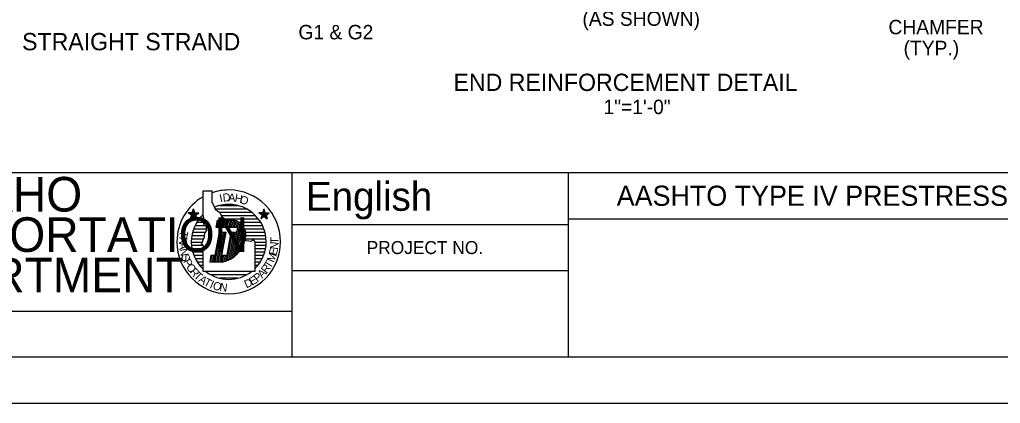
# Model space of a CAD drawing. Extents: x 0 to 45.3, y 0 to 31.4.
# Drawn here: x 21.72 to 35.92, y 0 to 5.54 of the extents above; entities that cross this region are included whole.
import ezdxf

# ---------------------------------------------------------------- set-up
doc = ezdxf.new("R2010")
doc.units = 0
for name, color, linetype in [('BORDER_ANNO_Cutsheet', 7, 'Continuous'), ('BRDG_ANNO_Anno-Sheet', 7, 'Continuous'), ('BRDG_ANNO_General-Notes', 7, 'Continuous')]:
    doc.layers.add(name, color=color, linetype=linetype)

msp = doc.modelspace()

# ---------------------------------------------------------------- linework, layer by layer
at = {"layer": 'BORDER_ANNO_Cutsheet'}
msp.add_lwpolyline([(0, 29.333), (45.333, 29.333), (45.333, 0), (0, 0)], close=True, dxfattribs=at)
at = {"layer": 'BRDG_ANNO_Anno-Sheet'}
for p, q in [((2, 3.333), (25.667, 3.333)), ((25.667, 0.667), (25.667, 3.333)), ((25.667, 3.333), (44.667, 3.333)), ((29.667, 0.667), (29.667, 3.333)), ((24.379, 2.723), (24.379, 3.071)), ((24.379, 3.071), (24.511, 3.071)), ((24.511, 2.897), (24.511, 3.071)), ((24.511, 2.897), (24.546, 2.835)), ((24.62, 2.859), (24.877, 2.859)), ((24.268, 2.72), (24.163, 2.754)), ((24.221, 2.754), (24.163, 2.754)), ((24.21, 2.72), (24.163, 2.754)), ((24.258, 2.754), (24.192, 2.664)), ((24.21, 2.72), (24.192, 2.664)), ((24.239, 2.698), (24.192, 2.664)), ((24.21, 2.72), (24.316, 2.754)), ((24.221, 2.754), (24.239, 2.809)), ((24.221, 2.754), (24.287, 2.664)), ((24.239, 2.698), (24.239, 2.809)), ((24.258, 2.754), (24.239, 2.809)), ((24.239, 2.698), (24.287, 2.664)), ((24.258, 2.754), (24.316, 2.754)), ((24.268, 2.72), (24.316, 2.754)), ((24.268, 2.72), (24.287, 2.664)), ((24.366, 2.715), (24.382, 2.715)), ((24.392, 2.675), (24.379, 2.723)), ((24.546, 2.835), (24.552, 2.807)), ((24.552, 2.807), (24.622, 2.758)), ((24.556, 2.811), (25.001, 2.811)), ((24.62, 2.763), (25.076, 2.763)), ((24.622, 2.758), (24.643, 2.703)), ((24.638, 2.715), (25.134, 2.715)), ((24.643, 2.703), (24.712, 2.647)), ((25.29, 2.72), (25.184, 2.754)), ((25.232, 2.72), (25.184, 2.754)), ((25.242, 2.754), (25.184, 2.754)), ((25.279, 2.754), (25.213, 2.664)), ((25.232, 2.72), (25.213, 2.664)), ((25.261, 2.698), (25.213, 2.664)), ((25.232, 2.72), (25.337, 2.754)), ((25.242, 2.754), (25.261, 2.809)), ((25.242, 2.754), (25.308, 2.664)), ((25.261, 2.698), (25.261, 2.809)), ((25.279, 2.754), (25.261, 2.809)), ((25.261, 2.698), (25.308, 2.664)), ((25.279, 2.754), (25.337, 2.754)), ((25.29, 2.72), (25.337, 2.754)), ((25.29, 2.72), (25.308, 2.664)), ((24.262, 2.571), (24.398, 2.571)), ((24.289, 2.619), (24.39, 2.619)), ((24.322, 2.667), (24.392, 2.667)), ((24.392, 2.633), (24.392, 2.675)), ((24.392, 2.598), (24.392, 2.633)), ((24.4, 2.571), (24.392, 2.598)), ((24.427, 2.557), (24.4, 2.571)), ((24.427, 2.522), (24.427, 2.557)), ((24.567, 2.542), (24.587, 2.647)), ((24.586, 2.542), (24.605, 2.647)), ((24.587, 2.647), (24.817, 2.647)), ((24.607, 2.542), (24.627, 2.647)), ((24.628, 2.542), (24.648, 2.647)), ((24.649, 2.542), (24.669, 2.647)), ((24.67, 2.542), (24.69, 2.647)), ((24.688, 2.667), (25.177, 2.667)), ((24.692, 2.542), (24.711, 2.647)), ((24.712, 2.542), (24.732, 2.647)), ((24.734, 2.542), (24.753, 2.647)), ((24.755, 2.542), (24.775, 2.647)), ((24.777, 2.542), (24.796, 2.647)), ((24.797, 2.542), (24.817, 2.647)), ((24.799, 2.099), (24.896, 2.616)), ((24.818, 2.542), (24.837, 2.642)), ((24.823, 2.114), (24.915, 2.603)), ((24.84, 2.542), (24.857, 2.636)), ((24.848, 2.134), (24.932, 2.585)), ((24.861, 2.542), (24.877, 2.627)), ((24.874, 2.158), (24.95, 2.566)), ((24.892, 2.619), (25.21, 2.619)), ((24.947, 2.571), (25.237, 2.571)), ((25.667, 2.583), (29.667, 2.583)), ((29.667, 2.667), (40.333, 2.667)), ((24.217, 2.427), (24.398, 2.427)), ((24.227, 2.475), (24.415, 2.475)), ((24.242, 2.523), (24.425, 2.523)), ((24.4, 2.438), (24.413, 2.467)), ((24.4, 2.404), (24.4, 2.438)), ((24.413, 2.467), (24.427, 2.501)), ((24.427, 2.501), (24.427, 2.522)), ((24.552, 2.14), (24.615, 2.473)), ((24.555, 2.042), (24.636, 2.473)), ((24.882, 2.542), (24.567, 2.542)), ((24.577, 2.042), (24.657, 2.473)), ((24.598, 2.042), (24.678, 2.473)), ((24.615, 2.473), (24.707, 2.473)), ((24.619, 2.042), (24.7, 2.473)), ((24.707, 2.473), (24.644, 2.14)), ((24.725, 2.14), (24.787, 2.473)), ((24.729, 2.063), (24.806, 2.473)), ((24.752, 2.073), (24.827, 2.473)), ((24.775, 2.084), (24.848, 2.473)), ((24.787, 2.473), (24.869, 2.473)), ((24.869, 2.473), (24.882, 2.542)), ((24.901, 2.187), (24.967, 2.542)), ((24.929, 2.225), (24.982, 2.509)), ((24.962, 2.29), (24.994, 2.46)), ((24.977, 2.523), (25.258, 2.523)), ((24.992, 2.475), (25.273, 2.475)), ((24.997, 2.427), (25.283, 2.427)), ((24.208, 2.331), (24.37, 2.331)), ((24.21, 2.379), (24.387, 2.379)), ((24.211, 2.283), (24.375, 2.283)), ((24.358, 2.3), (24.372, 2.334)), ((24.379, 2.279), (24.358, 2.3)), ((24.372, 2.334), (24.379, 2.362)), ((24.379, 2.362), (24.4, 2.404)), ((24.392, 2.258), (24.379, 2.279)), ((24.988, 2.37), (24.997, 2.355)), ((24.99, 2.379), (25.29, 2.379)), ((24.997, 2.355), (25.039, 2.348)), ((25.039, 2.348), (25.081, 2.342)), ((25.081, 2.342), (25.102, 2.369)), ((25.102, 2.369), (25.129, 2.328)), ((25.127, 2.331), (25.292, 2.331)), ((25.129, 2.328), (25.129, 1.903)), ((25.13, 2.283), (25.289, 2.283)), ((24.217, 2.235), (24.398, 2.235)), ((24.228, 2.188), (24.378, 2.188)), ((24.245, 2.139), (24.377, 2.139)), ((24.379, 2.203), (24.4, 2.223)), ((24.379, 1.903), (24.379, 2.203)), ((24.4, 2.244), (24.392, 2.258)), ((24.4, 2.223), (24.4, 2.244)), ((24.479, 2.042), (24.497, 2.14)), ((24.492, 2.042), (24.51, 2.14)), ((24.497, 2.14), (24.552, 2.14)), ((24.513, 2.042), (24.532, 2.14)), ((24.534, 2.042), (24.552, 2.14)), ((24.64, 2.042), (24.658, 2.14)), ((24.644, 2.14), (24.725, 2.14)), ((24.662, 2.043), (24.68, 2.14)), ((24.684, 2.049), (24.701, 2.14)), ((24.707, 2.056), (24.722, 2.14)), ((25.129, 2.235), (25.282, 2.235)), ((25.129, 2.188), (25.272, 2.188)), ((25.129, 2.139), (25.255, 2.139)), ((24.266, 2.091), (24.377, 2.091)), ((24.293, 2.043), (24.377, 2.043)), ((24.328, 1.995), (24.377, 1.995)), ((24.657, 2.042), (24.479, 2.042)), ((25.129, 2.091), (25.233, 2.091)), ((25.129, 2.043), (25.207, 2.043)), ((25.129, 1.995), (25.173, 1.995)), ((24.37, 1.948), (24.378, 1.948)), ((25.129, 1.903), (24.379, 1.903)), ((25.001, 1.855), (24.496, 1.855)), ((25.667, 1.917), (29.667, 1.917)), ((24.878, 1.807), (24.623, 1.807)), ((18.667, 1.333), (25.667, 1.333))]:
    msp.add_line(p, q, dxfattribs=at)
msp.add_lwpolyline([(2, 28.667), (44.667, 28.667), (44.667, 0.667), (2, 0.667)], close=True, dxfattribs=at)
for centre, radius, start, end in [((24.75, 2.333), 0.75, 119.6331, 180), ((24.75, 2.333), 0.75, 90, 108.596), ((24.75, 2.333), 0.75, 0, 90), ((24.75, 2.333), 0.542, 90, 112.1452), ((24.75, 2.333), 0.542, 0, 90), ((24.75, 2.333), 0.542, 133.1926, 180), ((24.778, 2.432), 0.219, 343.4981, 79.7362), ((24.75, 2.333), 0.75, 180, 270), ((24.75, 2.333), 0.542, 180.2644, 226.7946), ((24.58, 2.451), 0.416, 280.6479, 348.7719), ((24.75, 2.333), 0.75, 270, 0), ((24.75, 2.333), 0.542, 314.427, 0), ((24.75, 2.333), 0.542, 232.5658, 270), ((24.75, 2.333), 0.542, 270, 307.4536)]:
    msp.add_arc(centre, radius, start, end, dxfattribs=at)

# ---------------------------------------------------------------- texts
for s, height, p in [('IDAHO', 0.5, (20.512, 2.771)), ('English', 0.4167, (25.867, 2.782)), ('AASHTO TYPE IV PRESTRESSED GIRDER', 0.29084, (30.364, 2.854)), ('TRANSPORTATION', 0.5, (18.863, 2.188)), ('PROJECT NO.', 0.1875, (26.746, 2.157)), ('DEPARTMENT', 0.5, (19.492, 1.604))]:
    msp.add_text(s, height=height, dxfattribs=at).set_placement(p)
for s, rotation, p in [('I', 11.9519, (24.629, 2.904)), ('D', 5.2118, (24.668, 2.913)), ('A', 357.8718, (24.742, 2.917)), ('H', 349.6318, (24.829, 2.912)), ('O', 342.1917, (24.899, 2.897)), ('T', 259.4265, (24.051, 2.501)), ('R', 266.0275, (24.035, 2.41)), ('A', 273.764, (24.031, 2.321)), ('N', 83.1932, (25.46, 2.217)), ('T', 90.4926, (25.469, 2.306)), ('N', 280.3758, (24.038, 2.228)), ('S', 287.9279, (24.057, 2.138)), ('M', 67.7139, (25.401, 2.027)), ('E', 75.6105, (25.439, 2.129)), ('P', 295.4976, (24.087, 2.054)), ('O', 302.6446, (24.127, 1.973)), ('R', 52.3344, (25.298, 1.868)), ('T', 59.0362, (25.352, 1.94)), ('R', 309.9079, (24.178, 1.897)), ('T', 317.1211, (24.237, 1.828)), ('E', 30.5476, (25.087, 1.698)), ('P', 37.6656, (25.164, 1.746)), ('A', 45, (25.234, 1.801)), ('A', 324.6375, (24.304, 1.767)), ('T', 331.7503, (24.379, 1.716)), ('I', 337.0213, (24.466, 1.672)), ('O', 343.3287, (24.51, 1.654)), ('N', 351.6598, (24.612, 1.627)), ('D', 22.9887, (25.004, 1.661))]:
    msp.add_text(s, height=0.116, rotation=rotation, dxfattribs=at).set_placement(p)
at = {"layer": 'BRDG_ANNO_General-Notes'}
for s, height, p in [('(AS SHOWN)', 0.2083, (29.868, 5.454)), ('CHAMFER', 0.2083, (34.296, 5.332)), (' G1 & G2', 0.2083, (25.681, 5.259)), ('STRAIGHT STRAND', 0.25, (21.76, 5.101)), ('(TYP.)', 0.2083, (34.515, 5.03)), ('END REINFORCEMENT DETAIL', 0.25, (28.003, 4.513)), ('1"=1\'-0"', 0.2083, (30.173, 4.179))]:
    msp.add_text(s, height=height, dxfattribs=at).set_placement(p)

doc.saveas('drawing.dxf')
